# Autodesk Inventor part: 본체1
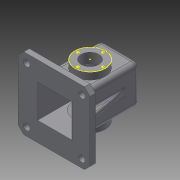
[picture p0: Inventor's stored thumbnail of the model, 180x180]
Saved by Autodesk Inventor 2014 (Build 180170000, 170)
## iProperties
Created: 2016-02
Part Number: 본체1
Material: Generic
Document SubType Name: Modeling
Designer: user
Density: 1 g/cm^3
Appearance: Default
Author: user
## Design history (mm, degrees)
sketch "Sketch1"
  geometry: L1 (-35, 55)-(35, 55); L2 (35, 55)-(35, -55); L3 (35, -55)-(-35, -55); L4 (-35, -55)-(-35, 55); L5 (35, -55)-(74.792, -55); L6 (74.792, -55)-(35, 45.791); 1 further point
  constraints: 12 end point, 2 parallel, 2 perpendicular, 1 horizontal, 1 point on line
  dimensions: "d44" = 111.544 deg angle of L5 L6
extrude "Extrusion1" new body sketch "Sketch1" stored distance "d4" = 70; taper "d5" = 0 deg
shell "Shell1" dims "d6" = 5
sketch "Sketch2"
  geometry: C1 r 27.5 at (0, 0); 1 further point
  constraints: 1 centre point, 1 coincident
  dimensions: "d7" = 55 diameter of C1
extrude "Extrusion2" join sketch "Sketch2" distance "d8" = 13; taper "d9" = 0 deg
sketch "Sketch3"
  geometry: 4 further points
hole "Hole1" sketch "Sketch3" at (0, 22.5), (-22.5, 0), (0, -22.5), (22.5, 0) diameter "d11" = 4; stored, may be unused: countersink angle "d15" = 82 deg, drill point angle "d17" = 118 deg; dims "d12" = 6, "d13" = 3.023, "d14" = 2, "d16" = 8
sketch "Sketch4"
  geometry: C1 r 2 at (0, -22.5) reference; C2 r 2 at (0, 22.5) reference; C3 r 2 at (-22.5, 0) reference; C4 r 2 at (22.5, 0) reference; C5 r 27.5 at (0, 0) reference
sketch "Sketch5"
  geometry: C1 r 27.5 at (0, 0) reference; C2 r 16 at (0, 0)
  constraints: 1 centre point, 1 coincident
  dimensions: "d18" = 32 diameter of C2
extrude "Extrusion3" cut sketch "Sketch5" stored distance "d19" = 13; taper "d20" = 0 deg
sketch "Sketch6"
  geometry: C1 r 16 at (30, -50) reference; C2 r 27.5 at (30, -52.5)
  constraints: 1 centre point
  dimensions: "d21" = 55 diameter of C2
extrude "Extrusion4" join sketch "Sketch6" distance "d22" = 7; taper "d23" = -45 deg
mirror "Mirror1"
sketch "Sketch7"
  geometry: L1 (65, -65)-(5, -65) reference; L2 (5, -65)-(5, -5) reference; L3 (5, -5)-(65, -5) reference; L4 (65, -5)-(65, -65) reference; L5 (-30, 30)-(100, 30); L6 (100, 30)-(100, -100); L7 (100, -100)-(-30, -100); L8 (-30, -100)-(-30, 30); 1 further point
  constraints: 8 end point, 2 parallel, 1 horizontal, 1 perpendicular
  dimensions: "d24" = 130 distance of L5.start L5.end; "d25" = 130 distance of L5.end L6.end; "d26" = 65 distance from line of L6 point (35, -35); "d27" = 65 distance from line of L5 point (35, -35)
extrude "Extrusion5" join sketch "Sketch7" distance "d28" = 10; taper "d29" = 0 deg
sketch "Sketch8"
  geometry: L1 (100, 100)-(-30, 100) reference; L2 (-15, 85)-(85, 85); L3 (85, 85)-(85, -15); L4 (85, -15)-(-15, -15); L5 (-15, -15)-(-15, 85); 1 further point
  constraints: 8 end point, 2 parallel, 1 horizontal, 1 perpendicular
  dimensions: "d30" = 100 distance of L2.start L2.end; "d31" = 100 distance of L2.end L3.end; "d32" = 15 horizontal distance of L1.start L2.end; "d33" = 15 distance from line of L1 L2.end
hole "Hole2" sketch "Sketch8" at (85, 85), (85, -15), (-15, -15), (-15, 85) diameter "d34" = 12; stored, may be unused: countersink angle "d38" = 82 deg, drill point angle "d40" = 118 deg; dims "d35" = 6, "d36" = 3.023, "d37" = 2, "d39" = 8
chamfer "Chamfer1" distance "d41" = 10; stored, may be unused: second distance "d42" = 2, angle "d43" = 45 deg
sketch "Sketch10"
  geometry: C1 r 20 at (35, 35); 1 further point
  constraints: 1 centre point, 1 coincident
  dimensions: "d51" = 40 diameter of C1
extrude "Extrusion7" join sketch "Sketch10" distance "d52" = 10; taper "d53" = 0 deg
sketch "Sketch11"
  geometry: C1 r 20 at (0, 0) reference
hole "Hole3" sketch "Sketch11" at (0, 0) diameter "d54" = 21; stored, may be unused: countersink angle "d58" = 82 deg, drill point angle "d60" = 118 deg; dims "d55" = 6, "d56" = 28, "d57" = 4, "d59" = 8
fillet "Fillet1" dims "d61" = 8
sketch "Sketch12"
  geometry: L1 (0, 0)-(-54, 0) reference; L2 (-32, 0)-(-22, 0); L3 (-22, 0)-(-22, 82.9); L4 (-22, 82.9)-(-32, 82.9); L5 (-32, 82.9)-(-32, 0); 1 further point
  constraints: 8 end point, 2 parallel, 1 horizontal, 1 perpendicular, 1 point on line
  dimensions: "d64" = 10 distance of L3.end L4.end; "d65" = 5 distance from line of L3 point (-27, 55)
extrude "Extrusion8" join sketch "Sketch12" distance "d66" = 15; taper "d67" = 0 deg
chamfer "Chamfer2" distance "d68" = 82; stored, may be unused: second distance "d69" = 15, angle "d70" = 80 deg
mirror "Mirror3"
chamfer "Chamfer3" distance "d71" = 15; stored, may be unused: second distance "d72" = 82, angle "d73" = 80 deg
fillet "Fillet4" dims "d74" = 3
fillet "Fillet5" dims "d75" = 3
fillet "Fillet6" dims "d76" = 3
sketch "Sketch13"
  geometry: L1 (-20.561, 39.864)-(23.303, 39.864); L2 (23.303, 39.864)-(23.303, 31.65); L3 (23.303, 31.65)-(-20.561, 31.65); L4 (-20.561, 31.65)-(-20.561, 39.864)
  constraints: 2 other
emboss "Emboss1" sketch "Sketch13" dims "d44" = 19.4681, "d78" = 0.5, "d79" = 0
body "Solid1"
